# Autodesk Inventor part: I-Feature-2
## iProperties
Created: 2006-07
Part Number: I-Feature-2
Document SubType Name: Modeling
Designer: xxs
Author: xxs
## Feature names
1. Drehung1 [Revolution]
2. Drehung2 [Revolution]
